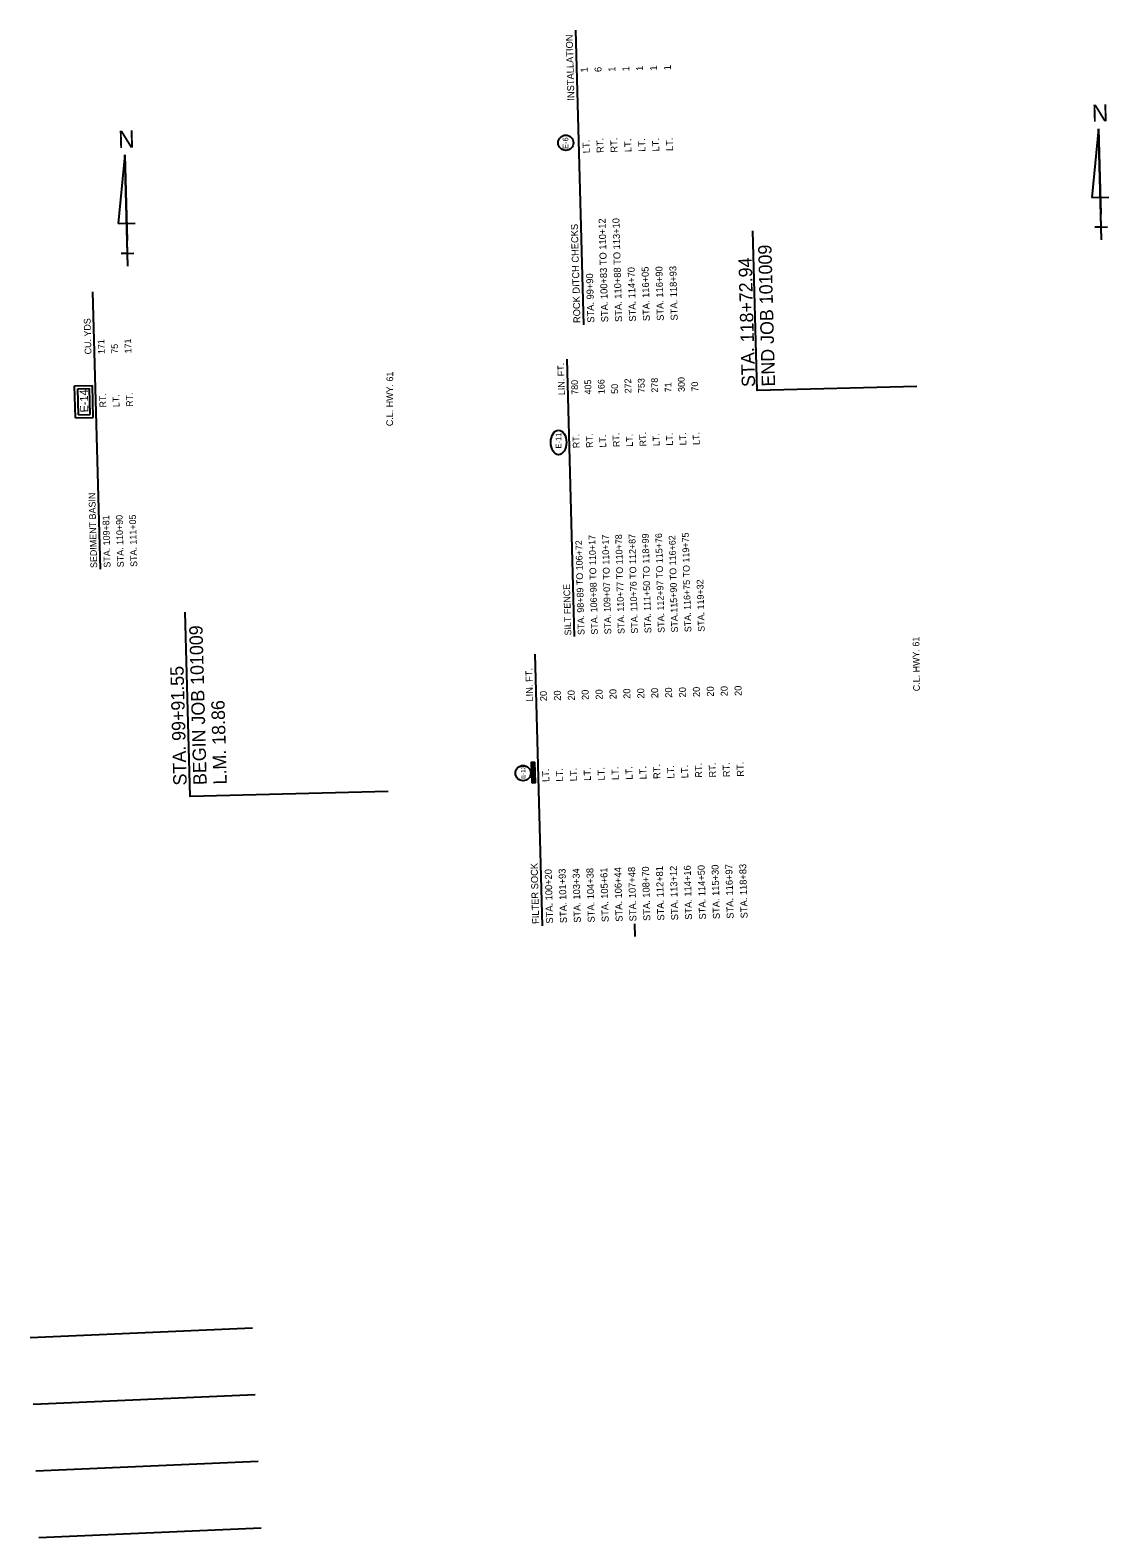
# Model space of a CAD drawing. Extents: x 1930579 to 1931598, y 596452 to 598587.
# Drawn here: x 1930579 to 1931549, y 596452 to 597807 of the extents above; entities that cross this region are included whole.
import ezdxf

# ---------------------------------------------------------------- set-up
doc = ezdxf.new("R2010")
doc.units = 0
for name, color, linetype in [('Default', 7, 'Continuous'), ('R_Erosion', 7, 'Continuous'), ('S_CAL_CORNER', 7, 'Continuous'), ('S_IRON_PIN', 7, 'Continuous'), ('S_SECTION_ANNOT', 7, 'Continuous')]:
    doc.layers.add(name, color=color, linetype=linetype)

msp = doc.modelspace()

# ---------------------------------------------------------------- linework, layer by layer
at = {"layer": 'Default'}
for p, q in [((1931077.3, 597542), (1931070.2, 597807)), ((1931040.2, 597001.9), (1931033.6, 597246))]:
    msp.add_line(p, q, dxfattribs=at)
at = {"layer": 'R_Erosion'}
for p, q in [((1930619.5, 597487.3), (1930635.5, 597487.7)), ((1930620.3, 597458.4), (1930619.5, 597487.3)), ((1930622.3, 597484.6), (1930632.9, 597484.9)), ((1930622.9, 597461.2), (1930622.3, 597484.6)), ((1930633.5, 597461.5), (1930632.9, 597484.9)), ((1930636.3, 597458.9), (1930635.5, 597487.7)), ((1930620.3, 597458.4), (1930636.3, 597458.9)), ((1930622.9, 597461.2), (1930633.5, 597461.5)), ((1931033.2, 597146), (1931030.3, 597148.7)), ((1931033.2, 597144.6), (1931030.4, 597147.3)), ((1931033.3, 597143.2), (1931030.4, 597145.9)), ((1931033.3, 597141.8), (1931030.4, 597144.5)), ((1931033.3, 597140.4), (1931030.5, 597143.1)), ((1931033.4, 597139), (1931030.5, 597141.7)), ((1931033.2, 597147.4), (1931031.6, 597148.9)), ((1931033.1, 597148.8), (1931033, 597149)), ((1931033.4, 597137.5), (1931030.6, 597140.2)), ((1931033.5, 597136.1), (1931030.6, 597138.8)), ((1931033.5, 597134.7), (1931030.6, 597137.4)), ((1931033.5, 597133.3), (1931030.7, 597136)), ((1931033.6, 597131.9), (1931030.7, 597134.6)), ((1931033.6, 597130.5), (1931030.7, 597133.2)), ((1931032.4, 597130.2), (1931030.8, 597131.8)), ((1931031, 597130.2), (1931030.8, 597130.4))]:
    msp.add_line(p, q, dxfattribs=at)
msp.add_lwpolyline([(1931030.8, 597130.2), (1931030.3, 597148.9), (1931033.1, 597149), (1931033.6, 597130.3)], close=True, dxfattribs=at)
for centre in [(1931061.1, 597705.7), (1931022.7, 597139.2)]:
    msp.add_circle(centre, 6.88, dxfattribs=at)
msp.add_ellipse((1931054.6, 597436.4), major_axis=(0, 11), ratio=0.638788, dxfattribs=at)
at = {"layer": 'S_CAL_CORNER'}
for p, q in [((1931540.1, 597718.4), (1931534, 597656.6)), ((1931542.8, 597618.4), (1931540.1, 597718.4)), ((1931540.1, 597718.4), (1931542.1, 597641.5)), ((1930664.6, 597694.9), (1930658.5, 597633.1)), ((1930667.3, 597594.9), (1930664.6, 597694.9)), ((1930664.6, 597694.9), (1930666.6, 597618)), ((1931534, 597656.6), (1931549.4, 597657)), ((1930658.5, 597633.1), (1930673.9, 597633.5)), ((1931536.7, 597629.8), (1931548.2, 597630.1)), ((1931542.4, 597629.9), (1931536.7, 597629.8)), ((1931542.8, 597618.4), (1931542.1, 597641.5)), ((1931542.8, 597618.4), (1931542.4, 597629.9)), ((1930667.3, 597594.9), (1930666.6, 597618)), ((1930661.2, 597606.3), (1930672.7, 597606.6)), ((1930667, 597606.4), (1930661.2, 597606.3)), ((1930667.3, 597594.9), (1930667, 597606.4)), ((1931123.5, 596992.3), (1931123.1, 597003.8))]:
    msp.add_line(p, q, dxfattribs=at)
at = {"layer": 'S_IRON_PIN'}
for p, q in [((1930642.7, 597322.5), (1930636, 597571.7)), ((1931069, 597261.9), (1931062.3, 597511.2))]:
    msp.add_line(p, q, dxfattribs=at)
for points in [[(1931376.8, 597486.8), (1931233.1, 597483), (1931229.3, 597626.6)], [(1930901.4, 597122.8), (1930723.5, 597118.1), (1930719, 597283.8)]]:
    msp.add_lwpolyline(points, dxfattribs=at)
at = {"layer": 'S_SECTION_ANNOT'}
for p, q in [((1930779.3, 596640.3), (1930579.5, 596631.6)), ((1930781.9, 596580.4), (1930582.1, 596571.7)), ((1930784.5, 596520.4), (1930584.7, 596511.8)), ((1930787.1, 596460.5), (1930587.3, 596451.8))]:
    msp.add_line(p, q, dxfattribs=at)

# ---------------------------------------------------------------- texts
at = {"layer": 'Default'}
for s, height, p in [('INSTALLATION', 6.25, (1931068.9, 597743.7)), ('1', 6.25, (1931080.8, 597769)), ('6', 6.25, (1931093.3, 597769.4)), ('1', 6.25, (1931105.8, 597769.7)), ('1', 6.25, (1931118.3, 597770)), ('1', 6.25, (1931130.7, 597770.4)), ('1', 6.25, (1931143.2, 597770.7)), ('1', 6.25, (1931155.7, 597771)), (' LT.', 6.25, (1931082.8, 597694.1)), (' RT.', 6.25, (1931095.3, 597694.4)), (' RT. ', 6.25, (1931107.8, 597694.7)), (' LT.', 6.25, (1931120.3, 597695.1)), (' LT.', 6.25, (1931132.8, 597695.4)), (' LT.', 6.25, (1931145.3, 597695.7)), (' LT.', 6.25, (1931157.7, 597696.1)), ('ROCK DITCH CHECKS', 6.25, (1931074.3, 597543.8)), ('STA. 100+83 TO 110+12', 6.25, (1931099.3, 597544.5)), ('STA. 110+88 TO 113+10 ', 6.25, (1931111.8, 597544.8)), ('STA. 118+72.94', 12, (1931231.4, 597486.4)), ('END JOB 101009', 12, (1931249.4, 597486.8)), ('STA. 99+90', 6.25, (1931086.8, 597544.1)), ('STA. 114+70', 6.25, (1931124.3, 597545.1)), ('STA. 116+05', 6.25, (1931136.8, 597545.5)), ('STA. 116+90', 6.25, (1931149.3, 597545.8)), ('STA. 118+93', 6.25, (1931161.8, 597546.1)), ('BEGIN JOB 101009', 12, (1930738.3, 597128.6)), ('STA. 99+91.55', 12, (1930720.3, 597128.2)), ('LIN. FT.', 6.25, (1931031.8, 597203.6)), ('20', 6.25, (1931044.3, 597203.9)), ('20', 6.25, (1931056.8, 597204.3)), ('20', 6.25, (1931069.3, 597204.6)), ('20', 6.25, (1931081.8, 597205)), ('20', 6.25, (1931094.3, 597205.3)), ('20', 6.25, (1931106.8, 597205.6)), ('20', 6.25, (1931119.3, 597206)), ('20', 6.25, (1931131.8, 597206.3)), ('20', 6.25, (1931144.3, 597206.6)), ('20', 6.25, (1931156.8, 597207)), ('20', 6.25, (1931169.3, 597207.3)), ('20', 6.25, (1931181.8, 597207.6)), ('20', 6.25, (1931194.3, 597208)), ('20', 6.25, (1931206.8, 597208.3)), ('20', 6.25, (1931219.3, 597208.6)), ('L.M. 18.86', 12, (1930756.3, 597129.1)), (' LT.', 6.25, (1931046.4, 597129)), (' LT.', 6.25, (1931058.8, 597129.3)), (' LT.', 6.25, (1931071.3, 597129.6)), (' LT.', 6.25, (1931083.8, 597130)), (' LT.', 6.25, (1931096.3, 597130.3)), (' LT.', 6.25, (1931108.8, 597130.7)), (' LT.', 6.25, (1931121.3, 597131)), (' LT.', 6.25, (1931133.8, 597131.3)), (' RT.', 6.25, (1931146.3, 597131.7)), (' LT.', 6.25, (1931158.8, 597132)), (' LT.', 6.25, (1931171.3, 597132.3)), (' RT.', 6.25, (1931183.8, 597132.7)), (' RT. ', 6.25, (1931196.3, 597133)), (' RT. ', 6.25, (1931208.8, 597133.3)), (' RT.', 6.25, (1931221.3, 597133.7)), ('FILTER SOCK   ', 6.25, (1931037.2, 597003.7)), ('STA. 100+20', 6.25, (1931049.7, 597004)), ('STA. 101+93', 6.25, (1931062.2, 597004.4)), ('STA. 103+34', 6.25, (1931074.7, 597004.7)), ('STA. 104+38', 6.25, (1931087.2, 597005)), ('STA. 105+61', 6.25, (1931099.7, 597005.4)), ('STA. 106+44', 6.25, (1931112.2, 597005.7)), ('STA. 107+48', 6.25, (1931124.7, 597006)), ('STA. 108+70', 6.25, (1931137.2, 597006.4)), ('STA. 112+81', 6.25, (1931149.7, 597006.7)), ('STA. 113+12', 6.25, (1931162.2, 597007)), ('STA. 114+16', 6.25, (1931174.7, 597007.4)), ('STA. 114+50', 6.25, (1931187.2, 597007.7)), ('STA. 115+30', 6.25, (1931199.7, 597008)), ('STA. 116+97', 6.25, (1931212.1, 597008.4)), ('STA. 118+83', 6.25, (1931224.6, 597008.7))]:
    msp.add_text(s, height=height, rotation=91.5377, dxfattribs=at).set_placement(p)
at = {"layer": 'R_Erosion'}
for s, height, rotation, p in [('E-6 ', 5, 90, (1931063.3, 597700.2)), ('E-14', 7.3, 91.5363, (1930631.9, 597463.5)), ('E-11', 5, 90, (1931057.1, 597431)), ('E-13', 4, 90, (1931024.7, 597133.9))]:
    msp.add_text(s, height=height, rotation=rotation, dxfattribs=at).set_placement(p)
at = {"layer": 'S_CAL_CORNER'}
for p in [(1931534.3, 597724.6), (1930658.8, 597701.1)]:
    msp.add_text('N', height=15.4, rotation=1.5377, dxfattribs=at).set_placement(p)
at = {"layer": 'S_IRON_PIN'}
for s, rotation, p in [('CU. YDS', 91.5377, (1930634.6, 597515.6)), ('171', 91.5377, (1930646.6, 597515.9)), ('75', 91.5377, (1930658.6, 597516.2)), ('171', 91.5377, (1930670.6, 597516.5)), ('LIN. FT.', 91.5377, (1931060.3, 597479)), ('C.L. HWY. 61', 89.7081, (1930905.7, 597451)), ('272', 91.5377, (1931120.2, 597480.6)), ('753', 91.5377, (1931132.2, 597480.9)), ('278', 91.5377, (1931144.2, 597481.2)), ('300', 91.5377, (1931168.2, 597481.9)), ('RT.', 91.5377, (1930647.9, 597467.9)), ('RT.', 91.5377, (1930671.9, 597468.5)), ('780', 91.5377, (1931072.3, 597479.3)), ('405', 91.5377, (1931084.2, 597479.6)), ('166', 91.5377, (1931096.2, 597479.9)), ('50', 91.5377, (1931108.2, 597480.2)), ('71', 91.5377, (1931156.2, 597481.5)), ('70', 91.5377, (1931180.2, 597482.2)), ('LT. ', 91.5377, (1930659.9, 597468.2)), ('RT.', 91.5377, (1931073.5, 597431.3)), ('RT.', 91.5377, (1931085.5, 597431.6)), ('LT.', 91.5377, (1931097.5, 597431.9)), ('RT.', 91.5377, (1931109.5, 597432.3)), ('LT.', 91.5377, (1931121.5, 597432.6)), ('RT.', 91.5377, (1931133.5, 597432.9)), ('LT.', 91.5377, (1931145.5, 597433.2)), ('LT.', 91.5377, (1931157.5, 597433.6)), ('LT.', 91.5377, (1931169.5, 597433.9)), ('LT.', 91.5377, (1931181.5, 597434.2)), ('SEDIMENT BASIN', 91.5377, (1930639.8, 597323.6)), ('STA. 111+05', 91.5377, (1930675.8, 597324.6)), ('STA. 109+81', 91.5377, (1930651.8, 597323.9)), ('STA. 110+90', 91.5377, (1930663.8, 597324.3)), ('STA. 98+89 TO 106+72', 91.5377, (1931078, 597263.4)), ('STA. 106+98 TO 110+17', 91.5377, (1931090, 597263.7)), ('STA. 109+07 TO 110+17', 91.5377, (1931102, 597264)), ('STA. 110+77 TO 110+78', 91.5377, (1931114, 597264.3)), ('STA. 110+76 TO 112+87', 91.5377, (1931126, 597264.6)), ('STA. 111+50 TO 118+99', 91.5377, (1931138, 597265)), ('STA. 112+97 TO 115+76', 91.5377, (1931150, 597265.3)), ('STA.115+90 TO 116+62', 91.5377, (1931162, 597265.6)), ('STA. 116+75 TO 119+75', 91.5377, (1931174, 597265.9)), ('SILT FENCE', 91.5377, (1931066.1, 597263)), ('STA. 119+32', 91.5377, (1931186, 597266.3)), ('C.L. HWY. 61', 90.6852, (1931379.5, 597212.8))]:
    msp.add_text(s, height=6, rotation=rotation, dxfattribs=at).set_placement(p)

doc.saveas('drawing.dxf')
